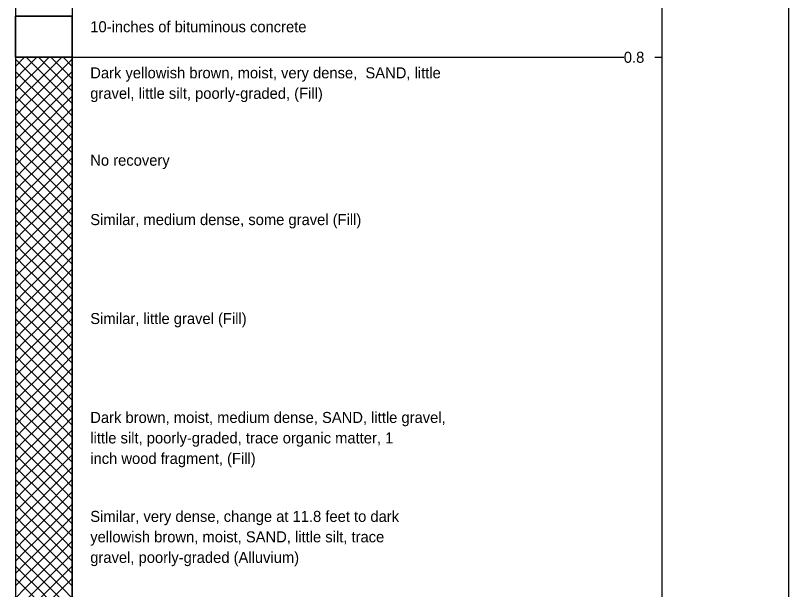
# Model space of a CAD drawing. Extents: x 9422 to 9552, y 6780 to 6860.
# Drawn here: x 9476.15 to 9491.78, y 6835.42 to 6847.03 of the extents above; entities that cross this region are included whole.
import ezdxf

# ---------------------------------------------------------------- set-up
doc = ezdxf.new("R2010")
doc.units = 0
doc.layers.add('7', color=7, linetype='Continuous')
doc.layers.add('8', color=7, linetype='Continuous')

msp = doc.modelspace()

# ---------------------------------------------------------------- linework, layer by layer
at = {"layer": '7'}
for p, q in [((9476.148, 6847.011), (9476.148, 6846.181)), ((9477.296, 6847.011), (9476.148, 6847.011)), ((9477.296, 6846.181), (9477.296, 6847.011)), ((9476.148, 6846.181), (9477.296, 6846.181)), ((9476.148, 6846.181), (9476.148, 6835.211)), ((9477.296, 6846.181), (9476.148, 6846.181)), ((9477.296, 6835.211), (9477.296, 6846.181)), ((9477.296, 6846.181), (9488.448, 6846.181)), ((9489.077, 6846.181), (9489.214, 6846.181))]:
    msp.add_line(p, q, dxfattribs=at)
for points in [[(9491.778, 6860.114), (9491.778, 6821.983)], [(9476.148, 6850.528), (9476.148, 6821.983)], [(9477.296, 6850.528), (9477.296, 6821.983)], [(9489.214, 6850.528), (9489.214, 6821.983)]]:
    msp.add_lwpolyline(points, dxfattribs=at)
at = {"layer": '8'}
for p, q in [((9476.148, 6845.996), (9476.332, 6846.181)), ((9476.347, 6845.946), (9476.148, 6846.145)), ((9476.347, 6845.946), (9476.582, 6846.181)), ((9476.597, 6845.946), (9476.362, 6846.181)), ((9476.597, 6845.946), (9476.832, 6846.181)), ((9476.847, 6845.946), (9476.612, 6846.181)), ((9476.847, 6845.946), (9477.082, 6846.181)), ((9477.097, 6845.946), (9476.862, 6846.181)), ((9477.097, 6845.946), (9477.296, 6846.145)), ((9477.296, 6845.996), (9477.112, 6846.181)), ((9476.148, 6845.746), (9476.347, 6845.946)), ((9476.347, 6845.696), (9476.148, 6845.895)), ((9476.597, 6845.696), (9476.347, 6845.946)), ((9476.347, 6845.696), (9476.597, 6845.946)), ((9476.847, 6845.696), (9476.597, 6845.946)), ((9476.597, 6845.696), (9476.847, 6845.946)), ((9477.097, 6845.696), (9476.847, 6845.946)), ((9476.847, 6845.696), (9477.097, 6845.946)), ((9477.296, 6845.746), (9477.097, 6845.946)), ((9477.097, 6845.696), (9477.296, 6845.895)), ((9476.148, 6845.496), (9476.347, 6845.696)), ((9476.597, 6845.446), (9476.347, 6845.696)), ((9476.347, 6845.446), (9476.597, 6845.696)), ((9476.847, 6845.446), (9476.597, 6845.696)), ((9476.597, 6845.446), (9476.847, 6845.696)), ((9477.097, 6845.446), (9476.847, 6845.696)), ((9476.847, 6845.446), (9477.097, 6845.696)), ((9477.296, 6845.496), (9477.097, 6845.696)), ((9476.347, 6845.446), (9476.148, 6845.645)), ((9477.097, 6845.446), (9477.296, 6845.645)), ((9476.148, 6845.246), (9476.347, 6845.446)), ((9476.347, 6845.196), (9476.148, 6845.395)), ((9476.597, 6845.196), (9476.347, 6845.446)), ((9476.347, 6845.196), (9476.597, 6845.446)), ((9476.847, 6845.196), (9476.597, 6845.446)), ((9476.597, 6845.196), (9476.847, 6845.446)), ((9477.097, 6845.196), (9476.847, 6845.446)), ((9476.847, 6845.196), (9477.097, 6845.446)), ((9477.296, 6845.246), (9477.097, 6845.446)), ((9477.097, 6845.196), (9477.296, 6845.395)), ((9476.148, 6844.996), (9476.347, 6845.196)), ((9476.597, 6844.946), (9476.347, 6845.196)), ((9476.347, 6844.946), (9476.597, 6845.196)), ((9476.847, 6844.946), (9476.597, 6845.196)), ((9476.597, 6844.946), (9476.847, 6845.196)), ((9477.097, 6844.946), (9476.847, 6845.196)), ((9476.847, 6844.946), (9477.097, 6845.196)), ((9477.296, 6844.996), (9477.097, 6845.196)), ((9476.347, 6844.946), (9476.148, 6845.145)), ((9477.097, 6844.946), (9477.296, 6845.145)), ((9476.148, 6844.746), (9476.347, 6844.946)), ((9476.347, 6844.696), (9476.148, 6844.895)), ((9476.597, 6844.696), (9476.347, 6844.946)), ((9476.347, 6844.696), (9476.597, 6844.946)), ((9476.847, 6844.696), (9476.597, 6844.946)), ((9476.597, 6844.696), (9476.847, 6844.946)), ((9477.097, 6844.696), (9476.847, 6844.946)), ((9476.847, 6844.696), (9477.097, 6844.946)), ((9477.296, 6844.746), (9477.097, 6844.946)), ((9477.097, 6844.696), (9477.296, 6844.895)), ((9476.148, 6844.496), (9476.347, 6844.696)), ((9476.347, 6844.446), (9476.148, 6844.645)), ((9476.597, 6844.446), (9476.347, 6844.696)), ((9476.347, 6844.446), (9476.597, 6844.696)), ((9476.847, 6844.446), (9476.597, 6844.696)), ((9476.597, 6844.446), (9476.847, 6844.696)), ((9477.097, 6844.446), (9476.847, 6844.696)), ((9476.847, 6844.446), (9477.097, 6844.696)), ((9477.296, 6844.496), (9477.097, 6844.696)), ((9477.097, 6844.446), (9477.296, 6844.645)), ((9476.148, 6844.246), (9476.347, 6844.446)), ((9476.597, 6844.196), (9476.347, 6844.446)), ((9476.347, 6844.196), (9476.597, 6844.446)), ((9476.847, 6844.196), (9476.597, 6844.446)), ((9476.597, 6844.196), (9476.847, 6844.446)), ((9477.097, 6844.196), (9476.847, 6844.446)), ((9476.847, 6844.196), (9477.097, 6844.446)), ((9477.296, 6844.246), (9477.097, 6844.446)), ((9476.347, 6844.196), (9476.148, 6844.395)), ((9477.097, 6844.196), (9477.296, 6844.395)), ((9476.148, 6843.996), (9476.347, 6844.196)), ((9476.347, 6843.946), (9476.148, 6844.145)), ((9476.597, 6843.946), (9476.347, 6844.196)), ((9476.347, 6843.946), (9476.597, 6844.196)), ((9476.847, 6843.946), (9476.597, 6844.196)), ((9476.597, 6843.946), (9476.847, 6844.196)), ((9477.097, 6843.946), (9476.847, 6844.196)), ((9476.847, 6843.946), (9477.097, 6844.196)), ((9477.296, 6843.996), (9477.097, 6844.196)), ((9477.097, 6843.946), (9477.296, 6844.145)), ((9476.148, 6843.746), (9476.347, 6843.946)), ((9476.597, 6843.696), (9476.347, 6843.946)), ((9476.347, 6843.696), (9476.597, 6843.946)), ((9476.847, 6843.696), (9476.597, 6843.946)), ((9476.597, 6843.696), (9476.847, 6843.946)), ((9477.097, 6843.696), (9476.847, 6843.946)), ((9476.847, 6843.696), (9477.097, 6843.946)), ((9477.296, 6843.746), (9477.097, 6843.946)), ((9476.347, 6843.696), (9476.148, 6843.895)), ((9477.097, 6843.696), (9477.296, 6843.895)), ((9476.148, 6843.496), (9476.347, 6843.696)), ((9476.347, 6843.446), (9476.148, 6843.645)), ((9476.597, 6843.446), (9476.347, 6843.696)), ((9476.347, 6843.446), (9476.597, 6843.696)), ((9476.847, 6843.446), (9476.597, 6843.696)), ((9476.597, 6843.446), (9476.847, 6843.696)), ((9477.097, 6843.446), (9476.847, 6843.696)), ((9476.847, 6843.446), (9477.097, 6843.696)), ((9477.296, 6843.496), (9477.097, 6843.696)), ((9477.097, 6843.446), (9477.296, 6843.645)), ((9476.148, 6843.246), (9476.347, 6843.446)), ((9476.347, 6843.196), (9476.148, 6843.395)), ((9476.597, 6843.196), (9476.347, 6843.446)), ((9476.347, 6843.196), (9476.597, 6843.446)), ((9476.847, 6843.196), (9476.597, 6843.446)), ((9476.597, 6843.196), (9476.847, 6843.446)), ((9477.097, 6843.196), (9476.847, 6843.446)), ((9476.847, 6843.196), (9477.097, 6843.446)), ((9477.296, 6843.246), (9477.097, 6843.446)), ((9477.097, 6843.196), (9477.296, 6843.395)), ((9476.148, 6842.996), (9476.347, 6843.196)), ((9476.597, 6842.946), (9476.347, 6843.196)), ((9476.347, 6842.946), (9476.597, 6843.196)), ((9476.847, 6842.946), (9476.597, 6843.196)), ((9476.597, 6842.946), (9476.847, 6843.196)), ((9477.097, 6842.946), (9476.847, 6843.196)), ((9476.847, 6842.946), (9477.097, 6843.196)), ((9477.296, 6842.996), (9477.097, 6843.196)), ((9476.347, 6842.946), (9476.148, 6843.145)), ((9477.097, 6842.946), (9477.296, 6843.145)), ((9476.148, 6842.746), (9476.347, 6842.946)), ((9476.347, 6842.696), (9476.148, 6842.895)), ((9476.597, 6842.696), (9476.347, 6842.946)), ((9476.347, 6842.696), (9476.597, 6842.946)), ((9476.847, 6842.696), (9476.597, 6842.946)), ((9476.597, 6842.696), (9476.847, 6842.946)), ((9477.097, 6842.696), (9476.847, 6842.946)), ((9476.847, 6842.696), (9477.097, 6842.946)), ((9477.296, 6842.746), (9477.097, 6842.946)), ((9477.097, 6842.696), (9477.296, 6842.895)), ((9476.148, 6842.496), (9476.347, 6842.696)), ((9476.597, 6842.446), (9476.347, 6842.696)), ((9476.347, 6842.446), (9476.597, 6842.696)), ((9476.847, 6842.446), (9476.597, 6842.696)), ((9476.597, 6842.446), (9476.847, 6842.696)), ((9477.097, 6842.446), (9476.847, 6842.696)), ((9476.847, 6842.446), (9477.097, 6842.696)), ((9477.296, 6842.496), (9477.097, 6842.696)), ((9476.347, 6842.446), (9476.148, 6842.645)), ((9477.097, 6842.446), (9477.296, 6842.645)), ((9476.148, 6842.246), (9476.347, 6842.446)), ((9476.347, 6842.196), (9476.148, 6842.395)), ((9476.597, 6842.196), (9476.347, 6842.446)), ((9476.347, 6842.196), (9476.597, 6842.446)), ((9476.847, 6842.196), (9476.597, 6842.446)), ((9476.597, 6842.196), (9476.847, 6842.446)), ((9477.097, 6842.196), (9476.847, 6842.446)), ((9476.847, 6842.196), (9477.097, 6842.446)), ((9477.296, 6842.246), (9477.097, 6842.446)), ((9477.097, 6842.196), (9477.296, 6842.395)), ((9476.148, 6841.996), (9476.347, 6842.196)), ((9476.347, 6841.946), (9476.148, 6842.145)), ((9476.597, 6841.946), (9476.347, 6842.196)), ((9476.347, 6841.946), (9476.597, 6842.196)), ((9476.847, 6841.946), (9476.597, 6842.196)), ((9476.597, 6841.946), (9476.847, 6842.196)), ((9477.097, 6841.946), (9476.847, 6842.196)), ((9476.847, 6841.946), (9477.097, 6842.196)), ((9477.296, 6841.996), (9477.097, 6842.196)), ((9477.097, 6841.946), (9477.296, 6842.145)), ((9476.148, 6841.746), (9476.347, 6841.946)), ((9476.597, 6841.696), (9476.347, 6841.946)), ((9476.347, 6841.696), (9476.597, 6841.946)), ((9476.847, 6841.696), (9476.597, 6841.946)), ((9476.597, 6841.696), (9476.847, 6841.946)), ((9477.097, 6841.696), (9476.847, 6841.946)), ((9476.847, 6841.696), (9477.097, 6841.946)), ((9477.296, 6841.746), (9477.097, 6841.946)), ((9476.347, 6841.696), (9476.148, 6841.895)), ((9477.097, 6841.696), (9477.296, 6841.895)), ((9476.148, 6841.496), (9476.347, 6841.696)), ((9476.347, 6841.446), (9476.148, 6841.645)), ((9476.597, 6841.446), (9476.347, 6841.696)), ((9476.347, 6841.446), (9476.597, 6841.696)), ((9476.847, 6841.446), (9476.597, 6841.696)), ((9476.597, 6841.446), (9476.847, 6841.696)), ((9477.097, 6841.446), (9476.847, 6841.696)), ((9476.847, 6841.446), (9477.097, 6841.696)), ((9477.296, 6841.496), (9477.097, 6841.696)), ((9477.097, 6841.446), (9477.296, 6841.645)), ((9476.148, 6841.246), (9476.347, 6841.446)), ((9476.597, 6841.196), (9476.347, 6841.446)), ((9476.347, 6841.196), (9476.597, 6841.446)), ((9476.847, 6841.196), (9476.597, 6841.446)), ((9476.597, 6841.196), (9476.847, 6841.446)), ((9477.097, 6841.196), (9476.847, 6841.446)), ((9476.847, 6841.196), (9477.097, 6841.446)), ((9477.296, 6841.246), (9477.097, 6841.446)), ((9476.347, 6841.196), (9476.148, 6841.395)), ((9477.097, 6841.196), (9477.296, 6841.395)), ((9476.148, 6840.996), (9476.347, 6841.196)), ((9476.347, 6840.946), (9476.148, 6841.145)), ((9476.597, 6840.946), (9476.347, 6841.196)), ((9476.347, 6840.946), (9476.597, 6841.196)), ((9476.847, 6840.946), (9476.597, 6841.196)), ((9476.597, 6840.946), (9476.847, 6841.196)), ((9477.097, 6840.946), (9476.847, 6841.196)), ((9476.847, 6840.946), (9477.097, 6841.196)), ((9477.296, 6840.996), (9477.097, 6841.196)), ((9477.097, 6840.946), (9477.296, 6841.145)), ((9476.148, 6840.746), (9476.347, 6840.946)), ((9476.347, 6840.696), (9476.148, 6840.895)), ((9476.597, 6840.696), (9476.347, 6840.946)), ((9476.347, 6840.696), (9476.597, 6840.946)), ((9476.847, 6840.696), (9476.597, 6840.946)), ((9476.597, 6840.696), (9476.847, 6840.946)), ((9477.097, 6840.696), (9476.847, 6840.946)), ((9476.847, 6840.696), (9477.097, 6840.946)), ((9477.296, 6840.746), (9477.097, 6840.946)), ((9477.097, 6840.696), (9477.296, 6840.895)), ((9476.148, 6840.496), (9476.347, 6840.696)), ((9476.597, 6840.446), (9476.347, 6840.696)), ((9476.347, 6840.446), (9476.597, 6840.696)), ((9476.847, 6840.446), (9476.597, 6840.696)), ((9476.597, 6840.446), (9476.847, 6840.696)), ((9477.097, 6840.446), (9476.847, 6840.696)), ((9476.847, 6840.446), (9477.097, 6840.696)), ((9477.296, 6840.496), (9477.097, 6840.696)), ((9476.347, 6840.446), (9476.148, 6840.645)), ((9477.097, 6840.446), (9477.296, 6840.645)), ((9476.148, 6840.246), (9476.347, 6840.446)), ((9476.347, 6840.196), (9476.148, 6840.395)), ((9476.597, 6840.196), (9476.347, 6840.446)), ((9476.347, 6840.196), (9476.597, 6840.446)), ((9476.847, 6840.196), (9476.597, 6840.446)), ((9476.597, 6840.196), (9476.847, 6840.446)), ((9477.097, 6840.196), (9476.847, 6840.446)), ((9476.847, 6840.196), (9477.097, 6840.446)), ((9477.296, 6840.246), (9477.097, 6840.446)), ((9477.097, 6840.196), (9477.296, 6840.395)), ((9476.148, 6839.996), (9476.347, 6840.196)), ((9476.597, 6839.946), (9476.347, 6840.196)), ((9476.347, 6839.946), (9476.597, 6840.196)), ((9476.847, 6839.946), (9476.597, 6840.196)), ((9476.597, 6839.946), (9476.847, 6840.196)), ((9477.097, 6839.946), (9476.847, 6840.196)), ((9476.847, 6839.946), (9477.097, 6840.196)), ((9477.296, 6839.996), (9477.097, 6840.196)), ((9476.347, 6839.946), (9476.148, 6840.145)), ((9477.097, 6839.946), (9477.296, 6840.145)), ((9476.148, 6839.746), (9476.347, 6839.946)), ((9476.347, 6839.696), (9476.148, 6839.895)), ((9476.597, 6839.696), (9476.347, 6839.946)), ((9476.347, 6839.696), (9476.597, 6839.946)), ((9476.847, 6839.696), (9476.597, 6839.946)), ((9476.597, 6839.696), (9476.847, 6839.946)), ((9477.097, 6839.696), (9476.847, 6839.946)), ((9476.847, 6839.696), (9477.097, 6839.946)), ((9477.296, 6839.746), (9477.097, 6839.946)), ((9477.097, 6839.696), (9477.296, 6839.895)), ((9476.148, 6839.496), (9476.347, 6839.696)), ((9476.347, 6839.446), (9476.148, 6839.645)), ((9476.597, 6839.446), (9476.347, 6839.696)), ((9476.347, 6839.446), (9476.597, 6839.696)), ((9476.847, 6839.446), (9476.597, 6839.696)), ((9476.597, 6839.446), (9476.847, 6839.696)), ((9477.097, 6839.446), (9476.847, 6839.696)), ((9476.847, 6839.446), (9477.097, 6839.696)), ((9477.296, 6839.496), (9477.097, 6839.696)), ((9477.097, 6839.446), (9477.296, 6839.645)), ((9476.148, 6839.246), (9476.347, 6839.446)), ((9476.597, 6839.196), (9476.347, 6839.446)), ((9476.347, 6839.196), (9476.597, 6839.446)), ((9476.847, 6839.196), (9476.597, 6839.446)), ((9476.597, 6839.196), (9476.847, 6839.446)), ((9477.097, 6839.196), (9476.847, 6839.446)), ((9476.847, 6839.196), (9477.097, 6839.446)), ((9477.296, 6839.246), (9477.097, 6839.446)), ((9476.347, 6839.196), (9476.148, 6839.395)), ((9477.097, 6839.196), (9477.296, 6839.395)), ((9476.148, 6838.996), (9476.347, 6839.196)), ((9476.347, 6838.946), (9476.148, 6839.145)), ((9476.597, 6838.946), (9476.347, 6839.196)), ((9476.347, 6838.946), (9476.597, 6839.196)), ((9476.847, 6838.946), (9476.597, 6839.196)), ((9476.597, 6838.946), (9476.847, 6839.196)), ((9477.097, 6838.946), (9476.847, 6839.196)), ((9476.847, 6838.946), (9477.097, 6839.196)), ((9477.296, 6838.996), (9477.097, 6839.196)), ((9477.097, 6838.946), (9477.296, 6839.145)), ((9476.148, 6838.746), (9476.347, 6838.946)), ((9476.597, 6838.696), (9476.347, 6838.946)), ((9476.347, 6838.696), (9476.597, 6838.946)), ((9476.847, 6838.696), (9476.597, 6838.946)), ((9476.597, 6838.696), (9476.847, 6838.946)), ((9477.097, 6838.696), (9476.847, 6838.946)), ((9476.847, 6838.696), (9477.097, 6838.946)), ((9477.296, 6838.746), (9477.097, 6838.946)), ((9476.347, 6838.696), (9476.148, 6838.895)), ((9477.097, 6838.696), (9477.296, 6838.895)), ((9476.148, 6838.496), (9476.347, 6838.696)), ((9476.347, 6838.446), (9476.148, 6838.645)), ((9476.597, 6838.446), (9476.347, 6838.696)), ((9476.347, 6838.446), (9476.597, 6838.696)), ((9476.847, 6838.446), (9476.597, 6838.696)), ((9476.597, 6838.446), (9476.847, 6838.696)), ((9477.097, 6838.446), (9476.847, 6838.696)), ((9476.847, 6838.446), (9477.097, 6838.696)), ((9477.296, 6838.496), (9477.097, 6838.696)), ((9477.097, 6838.446), (9477.296, 6838.645)), ((9476.148, 6838.246), (9476.347, 6838.446)), ((9476.347, 6838.196), (9476.148, 6838.395)), ((9476.597, 6838.196), (9476.347, 6838.446)), ((9476.347, 6838.196), (9476.597, 6838.446)), ((9476.847, 6838.196), (9476.597, 6838.446)), ((9476.597, 6838.196), (9476.847, 6838.446)), ((9477.097, 6838.196), (9476.847, 6838.446)), ((9476.847, 6838.196), (9477.097, 6838.446)), ((9477.296, 6838.246), (9477.097, 6838.446)), ((9477.097, 6838.196), (9477.296, 6838.395)), ((9476.148, 6837.996), (9476.347, 6838.196)), ((9476.597, 6837.946), (9476.347, 6838.196)), ((9476.347, 6837.946), (9476.597, 6838.196)), ((9476.847, 6837.946), (9476.597, 6838.196)), ((9476.597, 6837.946), (9476.847, 6838.196)), ((9477.097, 6837.946), (9476.847, 6838.196)), ((9476.847, 6837.946), (9477.097, 6838.196)), ((9477.296, 6837.996), (9477.097, 6838.196)), ((9476.347, 6837.946), (9476.148, 6838.145)), ((9477.097, 6837.946), (9477.296, 6838.145)), ((9476.148, 6837.746), (9476.347, 6837.946)), ((9476.347, 6837.696), (9476.148, 6837.895)), ((9476.597, 6837.696), (9476.347, 6837.946)), ((9476.347, 6837.696), (9476.597, 6837.946)), ((9476.847, 6837.696), (9476.597, 6837.946)), ((9476.597, 6837.696), (9476.847, 6837.946)), ((9477.097, 6837.696), (9476.847, 6837.946)), ((9476.847, 6837.696), (9477.097, 6837.946)), ((9477.296, 6837.746), (9477.097, 6837.946)), ((9477.097, 6837.696), (9477.296, 6837.895)), ((9476.148, 6837.496), (9476.347, 6837.696)), ((9476.597, 6837.446), (9476.347, 6837.696)), ((9476.347, 6837.446), (9476.597, 6837.696)), ((9476.847, 6837.446), (9476.597, 6837.696)), ((9476.597, 6837.446), (9476.847, 6837.696)), ((9477.097, 6837.446), (9476.847, 6837.696)), ((9476.847, 6837.446), (9477.097, 6837.696)), ((9477.296, 6837.496), (9477.097, 6837.696)), ((9476.347, 6837.446), (9476.148, 6837.645)), ((9477.097, 6837.446), (9477.296, 6837.645)), ((9476.148, 6837.246), (9476.347, 6837.446)), ((9476.347, 6837.196), (9476.148, 6837.395)), ((9476.597, 6837.196), (9476.347, 6837.446)), ((9476.347, 6837.196), (9476.597, 6837.446)), ((9476.847, 6837.196), (9476.597, 6837.446)), ((9476.597, 6837.196), (9476.847, 6837.446)), ((9477.097, 6837.196), (9476.847, 6837.446)), ((9476.847, 6837.196), (9477.097, 6837.446)), ((9477.296, 6837.246), (9477.097, 6837.446)), ((9477.097, 6837.196), (9477.296, 6837.395)), ((9476.148, 6836.996), (9476.347, 6837.196)), ((9476.347, 6836.946), (9476.148, 6837.145)), ((9476.597, 6836.946), (9476.347, 6837.196)), ((9476.347, 6836.946), (9476.597, 6837.196)), ((9476.847, 6836.946), (9476.597, 6837.196)), ((9476.597, 6836.946), (9476.847, 6837.196)), ((9477.097, 6836.946), (9476.847, 6837.196)), ((9476.847, 6836.946), (9477.097, 6837.196)), ((9477.296, 6836.996), (9477.097, 6837.196)), ((9477.097, 6836.946), (9477.296, 6837.145)), ((9476.148, 6836.746), (9476.347, 6836.946)), ((9476.597, 6836.696), (9476.347, 6836.946)), ((9476.347, 6836.696), (9476.597, 6836.946)), ((9476.847, 6836.696), (9476.597, 6836.946)), ((9476.597, 6836.696), (9476.847, 6836.946)), ((9477.097, 6836.696), (9476.847, 6836.946)), ((9476.847, 6836.696), (9477.097, 6836.946)), ((9477.296, 6836.746), (9477.097, 6836.946)), ((9476.347, 6836.696), (9476.148, 6836.895)), ((9477.097, 6836.696), (9477.296, 6836.895)), ((9476.148, 6836.496), (9476.347, 6836.696)), ((9476.347, 6836.446), (9476.148, 6836.645)), ((9476.597, 6836.446), (9476.347, 6836.696)), ((9476.347, 6836.446), (9476.597, 6836.696)), ((9476.847, 6836.446), (9476.597, 6836.696)), ((9476.597, 6836.446), (9476.847, 6836.696)), ((9477.097, 6836.446), (9476.847, 6836.696)), ((9476.847, 6836.446), (9477.097, 6836.696)), ((9477.296, 6836.496), (9477.097, 6836.696)), ((9477.097, 6836.446), (9477.296, 6836.645)), ((9476.148, 6836.246), (9476.347, 6836.446)), ((9476.597, 6836.196), (9476.347, 6836.446)), ((9476.347, 6836.196), (9476.597, 6836.446)), ((9476.847, 6836.196), (9476.597, 6836.446)), ((9476.597, 6836.196), (9476.847, 6836.446)), ((9477.097, 6836.196), (9476.847, 6836.446)), ((9476.847, 6836.196), (9477.097, 6836.446)), ((9477.296, 6836.246), (9477.097, 6836.446)), ((9476.347, 6836.196), (9476.148, 6836.395)), ((9477.097, 6836.196), (9477.296, 6836.395)), ((9476.148, 6835.996), (9476.347, 6836.196)), ((9476.347, 6835.946), (9476.148, 6836.145)), ((9476.597, 6835.946), (9476.347, 6836.196)), ((9476.347, 6835.946), (9476.597, 6836.196)), ((9476.847, 6835.946), (9476.597, 6836.196)), ((9476.597, 6835.946), (9476.847, 6836.196)), ((9477.097, 6835.946), (9476.847, 6836.196)), ((9476.847, 6835.946), (9477.097, 6836.196)), ((9477.296, 6835.996), (9477.097, 6836.196)), ((9477.097, 6835.946), (9477.296, 6836.145)), ((9476.148, 6835.746), (9476.347, 6835.946)), ((9476.347, 6835.696), (9476.148, 6835.895)), ((9476.597, 6835.696), (9476.347, 6835.946)), ((9476.347, 6835.696), (9476.597, 6835.946)), ((9476.847, 6835.696), (9476.597, 6835.946)), ((9476.597, 6835.696), (9476.847, 6835.946)), ((9477.097, 6835.696), (9476.847, 6835.946)), ((9476.847, 6835.696), (9477.097, 6835.946)), ((9477.296, 6835.746), (9477.097, 6835.946)), ((9477.097, 6835.696), (9477.296, 6835.895)), ((9476.148, 6835.496), (9476.347, 6835.696)), ((9476.597, 6835.446), (9476.347, 6835.696)), ((9476.347, 6835.446), (9476.597, 6835.696)), ((9476.847, 6835.446), (9476.597, 6835.696)), ((9476.597, 6835.446), (9476.847, 6835.696)), ((9477.097, 6835.446), (9476.847, 6835.696)), ((9476.847, 6835.446), (9477.097, 6835.696)), ((9477.296, 6835.496), (9477.097, 6835.696)), ((9476.347, 6835.446), (9476.148, 6835.645)), ((9477.097, 6835.446), (9477.296, 6835.645)), ((9476.148, 6835.246), (9476.347, 6835.446)), ((9476.582, 6835.211), (9476.347, 6835.446)), ((9476.362, 6835.211), (9476.597, 6835.446)), ((9476.832, 6835.211), (9476.597, 6835.446)), ((9476.612, 6835.211), (9476.847, 6835.446)), ((9477.082, 6835.211), (9476.847, 6835.446)), ((9476.862, 6835.211), (9477.097, 6835.446)), ((9477.296, 6835.246), (9477.097, 6835.446))]:
    msp.add_line(p, q, dxfattribs=at)
msp.add_lwpolyline([(9477.296, 6847.011), (9477.296, 6846.181), (9476.148, 6846.181), (9476.148, 6847.011)], close=True, dxfattribs=at)

# ---------------------------------------------------------------- texts
at = {"layer": '7'}
for s, p in [('10-inches of bituminous concrete', (9477.66, 6846.687)), ('0.8', (9488.448, 6846.069)), ('Dark yellowish brown, moist, very dense,  SAND, little', (9477.66, 6845.755)), ('gravel, little silt, poorly-graded, (Fill)', (9477.66, 6845.341)), ('No recovery', (9477.66, 6843.988)), ('Similar, medium dense, some gravel (Fill)', (9477.66, 6842.788)), ('Similar, little gravel (Fill)', (9477.66, 6840.788)), ('Dark brown, moist, medium dense, SAND, little gravel,', (9477.66, 6838.788)), ('little silt, poorly-graded, trace organic matter, 1', (9477.66, 6838.374)), ('inch wood fragment, (Fill)', (9477.66, 6837.959)), ('Similar, very dense, change at 11.8 feet to dark', (9477.66, 6836.788)), ('yellowish brown, moist, SAND, little silt, trace', (9477.66, 6836.374)), ('gravel, poorly-graded (Alluvium)', (9477.66, 6835.959))]:
    msp.add_text(s, height=0.2228, dxfattribs=at).set_placement(p)

doc.saveas('drawing.dxf')
